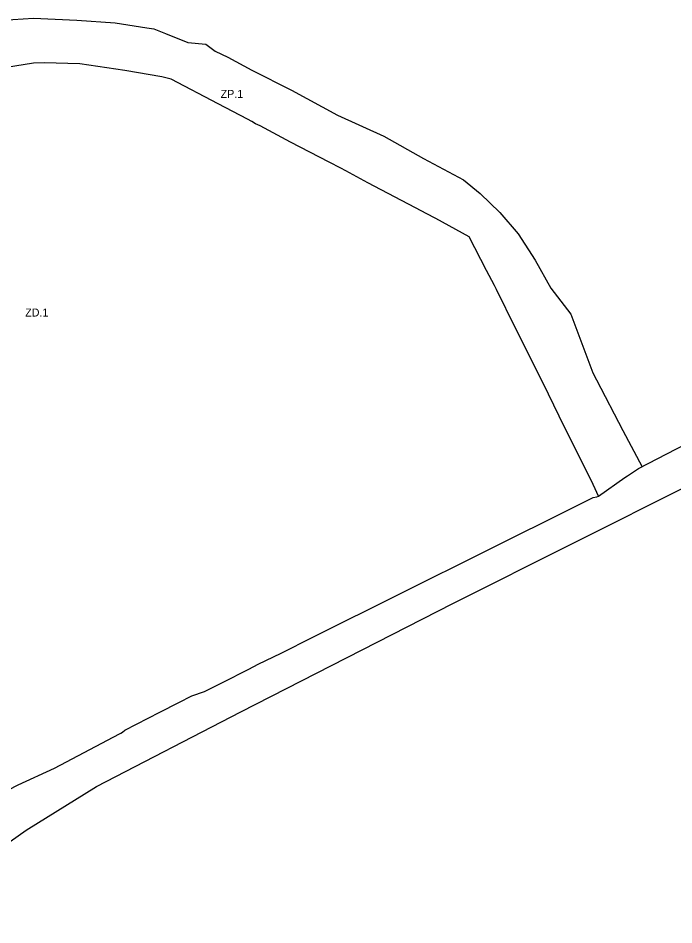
# Model space of a CAD drawing. Extents: x 7426626 to 7428617, y 5546366 to 5547802.
# Drawn here: x 7427476 to 7427886, y 5546612 to 5547178 of the extents above; entities that cross this region are included whole.
import ezdxf

# ---------------------------------------------------------------- set-up
doc = ezdxf.new("R2010")
doc.units = 0
doc.layers.add('LIN_Linie Rozgraniczajace', color=7, linetype='Continuous')
doc.layers.add('TXT_Oznaczenia Przeznaczenia', color=7, linetype='Continuous')

msp = doc.modelspace()

# ---------------------------------------------------------------- linework, layer by layer
at = {"layer": 'LIN_Linie Rozgraniczajace'}
for p, q in [((7427581.85, 5547162.89), (7427593.16, 5547161.79)), ((7427498.51, 5546709.68), (7427539.18, 5546731.21)), ((7427539.18, 5546731.21), (7427540.08, 5546731.66)), ((7427475.93, 5546699.23), (7427498.51, 5546709.68)), ((7427463.06, 5546692.82), (7427475.93, 5546699.23))]:
    msp.add_line(p, q, dxfattribs=at)
for points in [[(7427165.88, 5547017.92), (7427189.27, 5547031.72), (7427212.98, 5547045.35), (7427233.31, 5547058.28), (7427261.82, 5547075.07), (7427284.33, 5547089.02), (7427313.27, 5547107.33), (7427336.96, 5547122.74), (7427358.71, 5547137.11), (7427383.6, 5547151.95), (7427401.18, 5547159.94), (7427422.99, 5547169.37), (7427443.68, 5547173.93), (7427466.15, 5547176.95), (7427485.41, 5547178.13), (7427512.52, 5547176.96), (7427536.38, 5547175.21), (7427556.35, 5547172.06), (7427560.68, 5547171.39), (7427568.03, 5547168.57), (7427581.85, 5547162.89)], [(7427593.16, 5547161.79), (7427598.89, 5547157.55), (7427606.97, 5547153.82), (7427621.84, 5547145.7), (7427646.6, 5547133.19), (7427675.41, 5547117.48), (7427704.35, 5547104.32), (7427729.18, 5547090.49), (7427754.17, 5547077.24), (7427764.63, 5547068.65), (7427776.77, 5547056.74), (7427788.4, 5547043.41), (7427798.9, 5547027.08), (7427808.74, 5547009.55)], [(7427838.44, 5546879.69), (7427836.37, 5546884.1), (7427833.99, 5546889.68), (7427817.29, 5546922.68), (7427807.22, 5546943.24), (7427797.78, 5546962.57), (7427786.75, 5546984.54), (7427774.76, 5547008.63), (7427773.47, 5547011.25), (7427768.63, 5547020.57), (7427757.68, 5547041.61), (7427736.85, 5547052.92), (7427730.84, 5547056.18), (7427728.07, 5547057.62), (7427694.42, 5547075.37), (7427680.55, 5547082.73), (7427677.47, 5547084.38), (7427670.12, 5547088.25), (7427646.13, 5547100.75), (7427627.05, 5547110.78), (7427624.27, 5547112.22), (7427621.92, 5547113.48), (7427619.18, 5547114.94), (7427600.85, 5547124.7), (7427571.43, 5547140.11), (7427565.56, 5547141.57), (7427542.48, 5547145.35), (7427531.33, 5547147.02), (7427514.35, 5547149.56), (7427492.17, 5547150.2), (7427485.47, 5547149.96), (7427461.93, 5547146.24)], [(7427400.2, 5546611.86), (7427442.19, 5546643.82), (7427480.94, 5546671.03), (7427524.86, 5546698.24), (7427615.03, 5546744.99), (7427747.54, 5546812.47), (7427897.12, 5546887.45), (7428084.42, 5546980.69), (7428179.45, 5547028.08)], [(7427808.74, 5547009.55), (7427821.34, 5546993.21), (7427834.95, 5546956.65)], [(7427838.44, 5546879.69), (7427855, 5546891.19), (7427856.69, 5546892.3), (7427863.51, 5546896.78), (7427940.33, 5546936.53), (7428017.3, 5546977.31)], [(7427834.95, 5546956.65), (7427837.35, 5546952.34), (7427853.66, 5546920.68), (7427865.73, 5546897.93)], [(7427660, 5546791.6), (7427823.96, 5546873.06), (7427835.28, 5546878.69)], [(7427835.28, 5546878.69), (7427837.58, 5546879.13), (7427838.44, 5546879.69)], [(7427625.86, 5546774.66), (7427640.12, 5546781.45), (7427660, 5546791.6)], [(7427592.23, 5546757.65), (7427603.55, 5546763.29), (7427619.91, 5546771.57), (7427625.86, 5546774.66)], [(7427540.08, 5546731.66), (7427541.09, 5546732.16), (7427542.41, 5546733.37), (7427564.37, 5546744.76), (7427576.2, 5546750.72), (7427584.42, 5546754.79), (7427592.23, 5546757.65)]]:
    msp.add_lwpolyline(points, dxfattribs=at)

# ---------------------------------------------------------------- texts
at = {"layer": 'TXT_Oznaczenia Przeznaczenia'}
for s, p in [('ZP.1', (7427602.38, 5547128.31)), ('ZD.1', (7427480.23, 5546991.79))]:
    msp.add_text(s, height=5, dxfattribs=at).set_placement(p)

doc.saveas('drawing.dxf')
